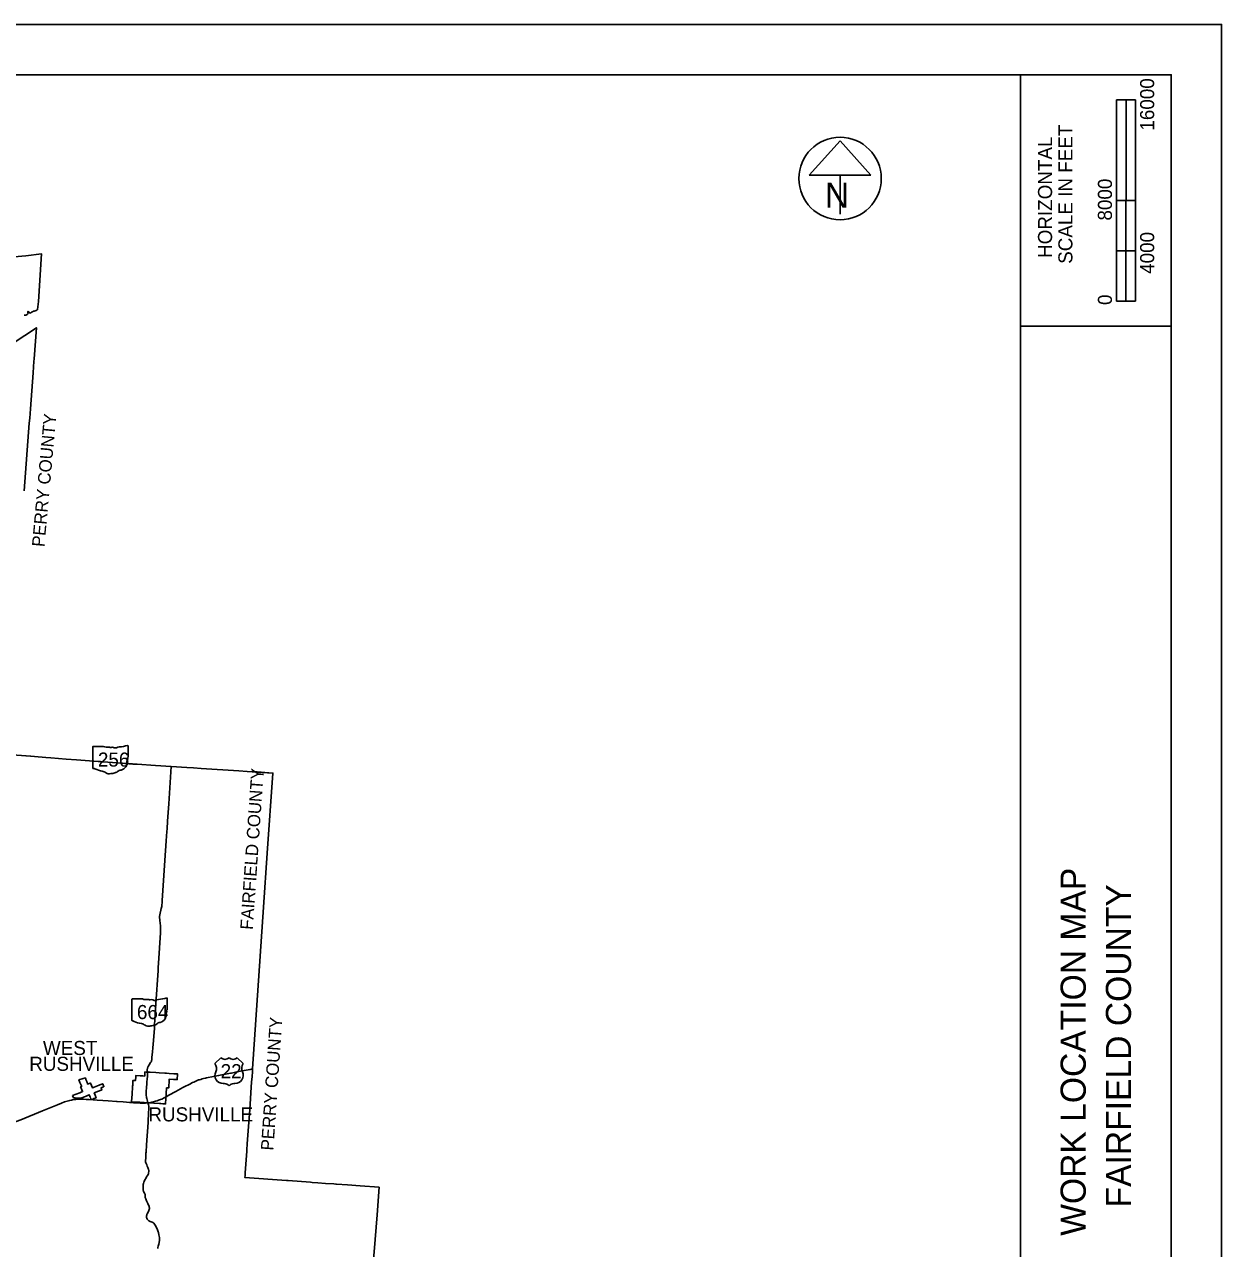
# Model space of a CAD drawing. Extents: x 1801177 to 2073177, y 551183 to 727183.
# Drawn here: x 1977949 to 2073177, y 629829 to 727183 of the extents above; entities that cross this region are included whole.
import ezdxf

# ---------------------------------------------------------------- set-up
doc = ezdxf.new("R2010")
doc.units = 0
for name, color, linetype in [('GM_X_Corporation', 7, 'Continuous'), ('GM_X_Corporation_Text', 7, 'Continuous'), ('GM_X_County', 7, 'Continuous'), ('GM_X_County_Text', 7, 'Continuous'), ('GM_X_State_Location', 7, 'Continuous'), ('GM_X_State_Route', 7, 'Continuous'), ('GM_X_State_Shield', 7, 'Continuous'), ('GM_X_US_Location', 7, 'Continuous'), ('GM_X_US_Route', 7, 'Continuous'), ('GM_X_US_Shield', 7, 'Continuous'), ('SH_Border', 7, 'Continuous'), ('SH_Cut_Line', 7, 'Continuous'), ('SH_Data', 7, 'Continuous'), ('SH_Masking', 7, 'Continuous'), ('SH_Text', 7, 'Continuous')]:
    doc.layers.add(name, color=color, linetype=linetype)

msp = doc.modelspace()

# ---------------------------------------------------------------- linework, layer by layer
at = {"layer": 'GM_X_Corporation'}
msp.add_lwpolyline([(1976528, 708641), (1978057, 708794), (1979311, 708937), (1979058, 705139), (1978993, 704509), (1978936, 704465), (1978868, 704437), (1978792, 704409), (1978716, 704390), (1978664, 704374), (1978590, 704338), (1978514, 704306), (1978456, 704250), (1978390, 704227), (1978330, 704273), (1978286, 704337), (1978220, 704359), (1978218, 704297), (1978234, 704225), (1978216, 704159), (1978167, 704107), (1978117, 704085), (1978052, 704076), (1978000, 704064), (1977932, 704064)], dxfattribs=at)
for points in [[(1987529, 643872), (1987620, 643866), (1987739, 643859), (1987841, 643852), (1987952, 643845), (1988387, 643819), (1988673, 643801), (1989115, 643774), (1989211, 643768), (1989240, 643767), (1989454, 643754), (1989826, 643733), (1990070, 643719), (1990101, 643717), (1990130, 643714), (1990129, 643694), (1990101, 643261), (1989795, 643280), (1989466, 643300), (1989454, 643095), (1989447, 642983), (1989441, 642872), (1989434, 642758), (1989430, 642696), (1989427, 642642), (1989425, 642608), (1989421, 642607), (1989419, 642607), (1989419, 642607), (1989415, 642607), (1989415, 642607), (1989412, 642606), (1989412, 642606), (1989412, 642606), (1989411, 642606), (1989409, 642606), (1989407, 642605), (1989405, 642605), (1989405, 642605), (1989404, 642605), (1989403, 642605), (1989402, 642605), (1989400, 642605), (1989399, 642604), (1989398, 642604), (1989396, 642604), (1989396, 642604), (1989395, 642604), (1989393, 642604), (1989391, 642604), (1989391, 642604), (1989390, 642603), (1989389, 642603), (1989389, 642603), (1989388, 642603), (1989385, 642603), (1989384, 642603), (1989382, 642603), (1989381, 642603), (1989378, 642602), (1989378, 642602), (1989375, 642602), (1989374, 642602), (1989373, 642602), (1989371, 642602), (1989370, 642602), (1989368, 642602), (1989367, 642602), (1989366, 642602), (1989364, 642602), (1989363, 642602), (1989360, 642602), (1989359, 642601), (1989357, 642601), (1989356, 642601), (1989353, 642601), (1989352, 642601), (1989350, 642601), (1989348, 642601), (1989346, 642601), (1989345, 642601), (1989343, 642601), (1989342, 642601), (1989341, 642601), (1989339, 642601), (1989337, 642601), (1989336, 642601), (1989336, 642601), (1989333, 642602), (1989332, 642602), (1989330, 642602), (1989329, 642602), (1989326, 642602), (1989326, 642602), (1989325, 642602), (1989322, 642602), (1989322, 642602), (1989321, 642602), (1989321, 642602), (1989319, 642602), (1989318, 642602), (1989315, 642602), (1989254, 642607), (1989228, 642155), (1989217, 641986), (1989202, 641756), (1989181, 641335), (1988961, 641349), (1988798, 641359), (1988696, 641367), (1988227, 641401), (1988101, 641409), (1987882, 641414), (1987467, 641441), (1987250, 641455), (1987137, 641463), (1986458, 641508), (1986470, 641574), (1986484, 641752), (1986518, 642168), (1986518, 642208), (1986542, 642581), (1986549, 642689), (1986553, 642745), (1986557, 642811), (1986563, 642898), (1986568, 642976), (1986569, 642986), (1986580, 643161), (1986582, 643205), (1986782, 643193), (1986803, 643488), (1986811, 643592), (1987141, 643573), (1987173, 643571), (1987366, 643559), (1987512, 643550), (1987515, 643550), (1987518, 643611), (1987523, 643695), (1987528, 643829)], [(1981777, 641999), (1982356, 642224), (1982567, 642306), (1982463, 642578), (1982437, 642644), (1982418, 642690), (1982507, 642725), (1982354, 643041), (1982282, 643232), (1982622, 643340), (1982798, 643396), (1982809, 643366), (1982821, 643338), (1982843, 643280), (1982866, 643219), (1982890, 643157), (1982897, 643140), (1982914, 643095), (1982937, 643034), (1982961, 642972), (1982976, 642907), (1983008, 642919), (1983014, 642922), (1983025, 642926), (1983030, 642928), (1983168, 642981), (1983199, 642993), (1983276, 642798), (1983351, 642610), (1983427, 642639), (1983495, 642666), (1983766, 642771), (1983893, 642820), (1983939, 642838), (1983948, 642841), (1984181, 642932), (1984212, 642855), (1984242, 642781), (1984242, 642781), (1984254, 642750), (1984272, 642705), (1984248, 642692), (1984091, 642631), (1984037, 642611), (1984103, 642441), (1984096, 642439), (1984042, 642418), (1983847, 642342), (1983844, 642341), (1983503, 642209), (1983575, 642024), (1983652, 641824), (1983502, 641763), (1983476, 641756), (1983384, 641720), (1983263, 641673), (1983252, 641669), (1983252, 641669), (1983250, 641674), (1983244, 641691), (1983229, 641730), (1983218, 641758), (1983203, 641795), (1983166, 641892), (1983131, 641982), (1983103, 642053), (1982905, 641977), (1982847, 641954), (1982718, 641904), (1982503, 641821), (1982446, 641796), (1982453, 641781), (1982435, 641782), (1982407, 641784), (1982298, 641792), (1982267, 641794), (1982172, 641800), (1981982, 641813), (1981934, 641816), (1981903, 641818), (1981844, 641822)]]:
    msp.add_lwpolyline(points, close=True, dxfattribs=at)
at = {"layer": 'GM_X_County'}
for points in [[(1976042, 701178), (1978895, 703062), (1978712, 700602), (1978706, 700391), (1978667, 699941), (1978642, 699484), (1978418, 696607), (1978363, 695865), (1978334, 695468), (1977935, 690100)], [(1977351, 669074), (1978441, 668981), (1979643, 668883), (1980046, 668846), (1981255, 668751), (1982076, 668690), (1983806, 668565), (1983991, 668552), (1984208, 668534), (1984949, 668481), (1986554, 668366), (1986914, 668342), (1988365, 668246), (1989608, 668172), (1990876, 668088), (1991394, 668058), (1991997, 668018), (1994999, 667826), (1995657, 667780), (1996458, 667729), (1997712, 667641), (1997257, 661263), (1996967, 656986), (1996091, 644115), (1996081, 643913), (1996050, 643471), (1996022, 643076), (1995867, 640886), (1995720, 638854), (1995677, 638161), (1995645, 637665), (1995639, 637582), (1995510, 635849), (1995499, 635641), (1995489, 635467), (1998790, 635243), (1998937, 635234), (2000696, 635097), (2000843, 635088), (2001274, 635043), (2001892, 635001), (2002560, 634963), (2002706, 634954), (2002764, 634944), (2003653, 634898), (2004663, 634817), (2006153, 634698), (2006000, 632497), (2005845, 630559), (2005566, 627003)]]:
    msp.add_lwpolyline(points, dxfattribs=at)
at = {"layer": 'GM_X_State_Route'}
for points in [[(1976201, 669170), (1976410, 669152), (1976776, 669121), (1977352, 669071), (1978442, 668978), (1979644, 668880), (1980047, 668843), (1981257, 668749), (1982077, 668687), (1983807, 668562), (1983992, 668550), (1984209, 668532), (1984950, 668478), (1986556, 668363), (1986915, 668339), (1988366, 668243), (1989609, 668170)], [(1988904, 657448), (1988907, 657500), (1989124, 660690), (1989229, 662265), (1989276, 662985), (1989293, 663203), (1989332, 663813), (1989430, 665191), (1989609, 668170)], [(1989609, 668170), (1990877, 668085), (1991395, 668055), (1991998, 668015), (1995000, 667823), (1995658, 667777), (1996459, 667726), (1997714, 667638)], [(1988770, 655208), (1988778, 655382), (1988770, 655542), (1988754, 655640), (1988738, 655770), (1988726, 655859), (1988710, 656003), (1988700, 656123), (1988702, 656247), (1988716, 656367), (1988748, 656507), (1988802, 656734), (1988830, 656861), (1988864, 657043), (1988882, 657170), (1988895, 657312), (1988904, 657448)], [(1988128, 645454), (1988130, 645479), (1988169, 645787), (1988212, 646362), (1988281, 647364), (1988300, 647617), (1988358, 648470), (1988407, 649294), (1988580, 651954), (1988589, 652163), (1988634, 652934), (1988734, 654532), (1988762, 654948), (1988770, 655208)], [(1987727, 643889), (1987724, 643908), (1987718, 643964), (1987716, 644013), (1987716, 644062), (1987719, 644094), (1987724, 644126), (1987731, 644158), (1987741, 644189), (1987752, 644219), (1987773, 644263), (1987796, 644305), (1987872, 644431), (1987982, 644614), (1988023, 644685), (1988044, 644730), (1988056, 644761), (1988066, 644793), (1988072, 644825), (1988079, 644891), (1988091, 645038), (1988128, 645454)], [(1987667, 642704), (1987678, 642860), (1987692, 643036), (1987717, 643359), (1987729, 643471), (1987744, 643618), (1987747, 643668), (1987745, 643733), (1987743, 643772), (1987739, 643811), (1987730, 643870), (1987727, 643889)], [(1987775, 641412), (1987735, 641556), (1987679, 641762), (1987660, 641842), (1987650, 641900), (1987635, 641992), (1987628, 642123), (1987634, 642250), (1987667, 642704)], [(1987847, 635993), (1987816, 636165), (1987802, 636203), (1987771, 636283), (1987722, 636383), (1987676, 636483), (1987627, 636588), (1987602, 636653), (1987586, 636728), (1987576, 636797), (1987593, 637050), (1987602, 637309), (1987607, 637412), (1987621, 637490), (1987663, 638083), (1987781, 639845), (1987828, 640664)], [(1987828, 640664), (1987840, 640878), (1987843, 640960), (1987838, 641091), (1987833, 641139), (1987810, 641268), (1987775, 641412)], [(1988549, 629823), (1988559, 629914), (1988588, 630014), (1988636, 630171), (1988666, 630298), (1988689, 630498), (1988680, 630712), (1988650, 630929), (1988613, 631090), (1988592, 631150), (1988523, 631309), (1988443, 631489), (1988354, 631679), (1988298, 631768), (1988227, 631851), (1988189, 631886), (1988153, 631910), (1988107, 631931), (1987948, 631980), (1987888, 632006), (1987838, 632040), (1987764, 632107), (1987721, 632166), (1987681, 632244), (1987665, 632291), (1987654, 632345), (1987655, 632416), (1987671, 632489), (1987695, 632543), (1987721, 632592), (1987784, 632714), (1987847, 632861), (1987871, 632938), (1987885, 633008), (1987882, 633057), (1987872, 633110), (1987856, 633163), (1987752, 633415), (1987656, 633630), (1987594, 633776), (1987570, 633837), (1987563, 633888), (1987562, 633960), (1987560, 634056), (1987546, 634115), (1987490, 634227), (1987426, 634366), (1987401, 634502), (1987388, 634603), (1987385, 634773), (1987396, 634915), (1987408, 635010), (1987431, 635094), (1987474, 635171), (1987535, 635285), (1987594, 635406), (1987665, 635527), (1987726, 635636), (1987790, 635714), (1987805, 635762), (1987823, 635835)], [(1987823, 635835), (1987824, 635840), (1987836, 635948), (1987847, 635993)]]:
    msp.add_lwpolyline(points, dxfattribs=at)
at = {"layer": 'GM_X_State_Shield'}
for p, q in [((1986190, 668920), (1986190, 669810)), ((1983388, 669738), (1983388, 668037)), ((1984237, 669767), (1983416, 669767)), ((1986190, 668920), (1986190, 668920)), ((1986500, 649659), (1986500, 647957)), ((1987348, 649688), (1986528, 649688)), ((1989302, 648840), (1989302, 649730)), ((1989301, 648840), (1989302, 648840))]:
    msp.add_line(p, q, dxfattribs=at)
for centre, major_axis, start_param, end_param in [((1985192, 672087), (2971, 0), 4.814394, 5.042369), ((1986159, 669813), (31.2, 0), 6.141152, 7.989035), ((1983421, 669742), (32.5, 0), 1.712693, 3.28349), ((1984432, 669965), (315, 0), 4.042523, 4.731795), ((1984536, 668812), (1130, 0), 1.404758, 1.657858), ((1984793, 669751), (90.8, 0), 3.836095, 5.185415), ((1984926, 669554), (189, 0), 0.950623, 2.079405), ((1985170, 669824), (227, 0), 4.081561, 5.145723), ((1985571, 669248), (598, 0), 1.699011, 2.107814), ((1986183, 668854), (48.3, 0), 1.883978, 3.671073), ((1985876, 668742), (290, 0), 5.934695, 6.695948), ((1986157, 668916), (33.4, 0), 5.05454, 6.418171), ((1983421, 668033), (32.7, 0), 3.00124, 4.508301), ((1983426, 668207), (250, 0), 4.665946, 4.897461), ((1983477, 667939), (90.1, 0), 0.519207, 1.627899), ((1984615, 669467), (2146, 0), 4.195997, 4.488961), ((1985672, 667559), (407, 0), 1.647645, 2.488434), ((1985359, 668434), (743, 0), 5.101752, 6.440018), ((1986302, 668547), (211, 0), 2.387724, 3.262537), ((1983975, 667273), (671, 0), 0.823519, 1.323587), ((1984701, 667930), (426, 0), 4.026481, 4.996735), ((1984947, 667342), (350, 0), 1.495662, 1.94098), ((1984978, 667803), (227, 0), 4.691044, 5.507374), ((1985184, 667638), (63.9, 0), 1.147584, 2.315152), ((1985156, 667872), (240, 0), 4.937069, 5.64225), ((1986532, 649662), (32.5, 0), 1.712693, 3.28349), ((1987543, 649885), (315, 0), 4.042523, 4.731795), ((1987648, 648733), (1130, 0), 1.404758, 1.657858), ((1987904, 649671), (90.8, 0), 3.836095, 5.185415), ((1988038, 649474), (189, 0), 0.950623, 2.079405), ((1988281, 649744), (227, 0), 4.081561, 5.145723), ((1988683, 649168), (598, 0), 1.699011, 2.107814), ((1988304, 652007), (2971, 0), 4.814394, 5.042369), ((1989271, 649734), (31.2, 0), 6.141152, 7.989035), ((1988470, 648354), (743, 0), 5.101752, 6.440018), ((1989413, 648468), (211, 0), 2.387724, 3.262537), ((1989294, 648775), (48.3, 0), 1.883978, 3.671073), ((1988987, 648662), (290, 0), 5.934695, 6.695948), ((1989268, 648837), (33.4, 0), 5.05454, 6.418171), ((1986532, 647954), (32.7, 0), 3.00124, 4.508301), ((1986537, 648128), (250, 0), 4.665946, 4.897461), ((1986588, 647859), (90.1, 0), 0.519207, 1.627899), ((1987726, 649388), (2146, 0), 4.195997, 4.488961), ((1987086, 647193), (671, 0), 0.823519, 1.323587), ((1987812, 647851), (426, 0), 4.026481, 4.996735), ((1988059, 647263), (350, 0), 1.495662, 1.94098), ((1988090, 647723), (227, 0), 4.691044, 5.507374), ((1988295, 647559), (63.9, 0), 1.147584, 2.315152), ((1988268, 647792), (240, 0), 4.937069, 5.64225), ((1988783, 647480), (407, 0), 1.647645, 2.488434)]:
    msp.add_ellipse(centre, major_axis=major_axis, ratio=0.8, start_param=start_param, end_param=end_param, dxfattribs=at)
at = {"layer": 'GM_X_US_Route'}
for points in [[(1992352, 643376), (1992441, 643396), (1992998, 643517), (1993393, 643581), (1994337, 643767), (1994412, 643782), (1994852, 643870), (1995591, 644015), (1995894, 644074), (1996092, 644112)], [(1989216, 641894), (1989438, 642015), (1989987, 642308), (1990560, 642627)], [(1990560, 642627), (1990652, 642678), (1991093, 642900), (1991326, 643021), (1991433, 643070), (1991643, 643166), (1991737, 643209), (1991806, 643236), (1991883, 643256), (1991975, 643283), (1992091, 643314), (1992190, 643340), (1992352, 643376)], [(1980898, 641392), (1981144, 641487), (1981252, 641524), (1981457, 641584), (1981553, 641608), (1981682, 641635), (1981775, 641652), (1981801, 641656), (1981925, 641674), (1982039, 641687), (1982132, 641697), (1982263, 641705), (1982441, 641710), (1982521, 641710), (1982644, 641706), (1982865, 641692), (1983068, 641679), (1983737, 641632), (1984171, 641599)], [(1984171, 641599), (1984596, 641567), (1985282, 641519)], [(1987775, 641412), (1987878, 641426), (1987988, 641445), (1988081, 641462), (1988194, 641487), (1988290, 641512), (1988385, 641539), (1988511, 641578), (1988620, 641616), (1988774, 641676), (1988865, 641715), (1989073, 641816), (1989216, 641894)], [(1976677, 639673), (1977007, 639814), (1977656, 640075), (1979389, 640789), (1980565, 641262), (1980898, 641392)], [(1985282, 641519), (1985318, 641517), (1985806, 641484)], [(1985806, 641484), (1986057, 641467), (1986311, 641446)], [(1986311, 641446), (1986414, 641438), (1986613, 641422), (1986873, 641403), (1987149, 641387), (1987262, 641383), (1987360, 641383), (1987474, 641386), (1987588, 641393), (1987701, 641403), (1987775, 641412)]]:
    msp.add_lwpolyline(points, dxfattribs=at)
at = {"layer": 'GM_X_US_Shield'}
for p, q in [((1993571, 645007), (1993104, 644540)), ((1995346, 644540), (1994879, 645007)), ((1993758, 642952), (1993851, 642952)), ((1994598, 642952), (1994692, 642952))]:
    msp.add_line(p, q, dxfattribs=at)
for centre, radius, start, end in [((1992569, 644165), 654, 334.54712, 35.00093), ((1993898, 645340), 467, 225.573, 314.427), ((1994552, 645340), 467, 225.573, 314.427), ((1995881, 644165), 654, 144.99907, 205.45288), ((1993751, 643606), 654, 154.83192, 270.63826), ((1994699, 643606), 654, 269.36174, 25.16808), ((1993851, 642485), 467, 36.8699, 90), ((1994598, 642485), 467, 90, 143.1301)]:
    msp.add_arc(centre, radius, start, end, dxfattribs=at)
at = {"layer": 'SH_Border'}
for p, q in [((2057177, 555183), (2057177, 723183)), ((2057177, 703183), (2069177, 703183))]:
    msp.add_line(p, q, dxfattribs=at)
msp.add_lwpolyline([(1813177, 723183), (2069177, 723183), (2069177, 555183), (1813177, 555183)], close=True, dxfattribs=at)
at = {"layer": 'SH_Cut_Line'}
msp.add_lwpolyline([(1801177, 551183), (2073177, 551183), (2073177, 727183), (1801177, 727183)], close=True, dxfattribs=at)
at = {"layer": 'SH_Data'}
for p, q in [((2064830, 705183), (2064830, 721183)), ((2066330, 721183), (2064830, 721183)), ((2064830, 713183), (2064830, 721183)), ((2064830, 721183), (2065577, 721183)), ((2065577, 721183), (2065584, 721183)), ((2065584, 721183), (2065584, 713183)), ((2066330, 721183), (2066330, 705183)), ((2065584, 713183), (2064830, 713183)), ((2066324, 713183), (2065577, 713183)), ((2065577, 713183), (2065577, 709183)), ((2066324, 709183), (2066324, 713183)), ((2065577, 709183), (2064830, 709183)), ((2064830, 709183), (2064830, 705183)), ((2065577, 705183), (2065577, 709183)), ((2065577, 709183), (2066324, 709183)), ((2066330, 705183), (2064830, 705183)), ((2064830, 705183), (2065577, 705183))]:
    msp.add_line(p, q, dxfattribs=at)
at = {"layer": 'SH_Masking'}
msp.add_circle((2042831, 714932), 3280, dxfattribs=at)
at = {"layer": 'SH_Text'}
for p, q in [((2042831, 717922), (2040370, 715192)), ((2045291, 715192), (2042831, 717922)), ((2040370, 715192), (2045291, 715192)), ((2042831, 715192), (2042831, 712098))]:
    msp.add_line(p, q, dxfattribs=at)
msp.add_circle((2042831, 714932), 3280, dxfattribs=at)

# ---------------------------------------------------------------- texts
at = {"layer": 'GM_X_Corporation_Text'}
for s, p in [('WEST', (1979419, 645220)), ('RUSHVILLE', (1978330, 643960)), ('RUSHVILLE', (1987809, 639938))]:
    msp.add_text(s, height=1120, rotation=0.00001, dxfattribs=at).set_placement(p)
at = {"layer": 'GM_X_County_Text'}
for s, rotation, p in [('PERRY COUNTY', 84.79025, (1979533, 685599)), ('FAIRFIELD COUNTY', 86.01588, (1996106, 655157)), ('PERRY COUNTY', 86.07844, (1997747, 637600))]:
    msp.add_text(s, height=1000, rotation=rotation, dxfattribs=at).set_placement(p)
at = {"layer": 'GM_X_State_Location'}
for s, p in [('256', (1984576, 668289)), ('664', (1987234, 635025))]:
    msp.add_text(s, height=1, rotation=0.00001, dxfattribs=at).set_placement(p)
for s, p in [('s', (1984929, 668362)), ('r', (1984929, 668362)), ('s', (1987587, 635098)), ('r', (1987587, 635098))]:
    msp.add_text(s, height=1, dxfattribs=at).set_placement(p)
at = {"layer": 'GM_X_State_Shield'}
for s, p in [('256', (1983792, 668157)), ('664', (1986895, 648077))]:
    msp.add_text(s, height=1120.7, dxfattribs=at).set_placement(p)
at = {"layer": 'GM_X_US_Location'}
for s in ['0', '/']:
    msp.add_text(s, height=1, dxfattribs=at).set_placement((1994225, 643715))
msp.add_text('22', height=1, rotation=0.00001, dxfattribs=at).set_placement((1994018, 643508))
at = {"layer": 'GM_X_US_Shield'}
msp.add_text('22', height=1120.7, dxfattribs=at).set_placement((1993555, 643373))
at = {"layer": 'SH_Data'}
for s, height, p in [('16000', 1120, (2067820, 718742)), ('SCALE IN FEET', 1120, (2061317, 708148)), ('HORIZONTAL', 1120, (2059697, 708617)), ('8000', 1120, (2064461, 711589)), ('4000', 1120, (2067820, 707351)), ('0', 1120, (2064461, 704873)), ('WORK LOCATION MAP', 2000, (2062377, 630841)), ('FAIRFIELD COUNTY', 2000, (2065977, 633097))]:
    msp.add_text(s, height=height, rotation=90, dxfattribs=at).set_placement(p)
at = {"layer": 'SH_Text'}
msp.add_text('N', height=2000, dxfattribs=at).set_placement((2041620, 712601))

doc.saveas('drawing.dxf')
